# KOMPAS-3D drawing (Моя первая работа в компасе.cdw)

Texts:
  Вариант 10
  Елена
  Выше всяких похвал
  ООн
  Жаренкова
  Подгорный
  сталь
  НТИ МГУДТ
  Вариант 10-
Dimensions and other numbers on the sheet: 15; 25; 50; 35; 20; 10; 1:1; 1; 04.04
